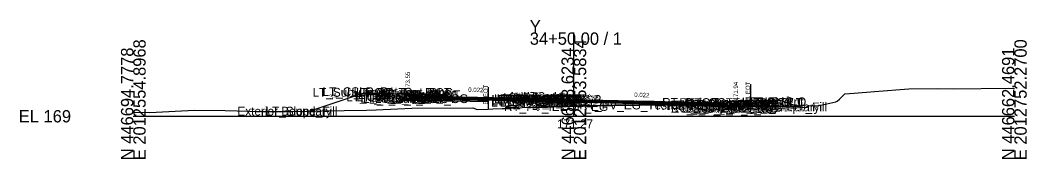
# Model space of a CAD drawing. Extents: x -26 to 3203, y -10 to 9532.
# Drawn here: x 1974.3 to 2202.8, y 8490.3 to 8521.8 of the extents above; entities that cross this region are included whole.
import ezdxf

# ---------------------------------------------------------------- set-up
doc = ezdxf.new("R2010")
doc.units = 0
for name, color, linetype in [('Default', 7, 'Continuous'), ('Exist CMT Pavement', 7, 'Continuous'), ('Exist Cross Section Cell', 7, 'Continuous'), ('Exist XS Center Line Elevation Label', 7, 'Continuous'), ('Exist XS Ground Line', 7, 'Continuous'), ('Prop CMT Conc Surface', 7, 'Continuous'), ('Prop CMT Concrete Structures', 7, 'Continuous'), ('Prop CMT Pvmt Course 1', 7, 'Continuous'), ('Prop CMT Pvmt Course 1 CG', 7, 'Continuous'), ('Prop CMT Pvmt Course 1 Wedge', 7, 'Continuous'), ('Prop CMT Pvmt Course 2', 7, 'Continuous'), ('Prop CMT Pvmt Course 2 Wedge', 7, 'Continuous'), ('Prop CMT Pvmt Course 3', 7, 'Continuous'), ('Prop CMT Pvmt Course 3 Wedge', 7, 'Continuous'), ('Prop CMT Pvmt Surface', 7, 'Continuous'), ('Prop CMT Pvmt Wedge Surface 1', 7, 'Continuous'), ('Prop CMT Pvmt Wedge Surface 2', 7, 'Continuous'), ('Prop CMT Pvmt Wedge Surface 3', 7, 'Continuous'), ('Prop CMT Slope Grass', 7, 'Continuous'), ('Prop CMT Subgrade Earthwork', 7, 'Continuous'), ('Prop XS Hydro Elevations', 7, 'Continuous'), ('Prop XS Label Text', 7, 'Continuous'), ('Prop XS SE Text', 7, 'Continuous'), ('Prop XS Side Slope Text', 7, 'Continuous'), ('Scratch_Level_0', 7, 'Continuous')]:
    doc.layers.add(name, color=color, linetype=linetype)

msp = doc.modelspace()

# ---------------------------------------------------------------- linework, layer by layer
at = {"layer": 'Exist CMT Pavement'}
for points in [[(2114.88, 8502.55), (2096, 8502.18)], [(2132.75, 8502.44), (2114.88, 8502.55)]]:
    msp.add_lwpolyline(points, dxfattribs=at)
at = {"layer": 'Exist Cross Section Cell'}
for p, q in [((2100, 8500), (2100, 8519.04)), ((2000, 8500), (2100, 8500)), ((2100, 8500), (2200, 8500))]:
    msp.add_line(p, q, dxfattribs=at)
at = {"layer": 'Exist XS Ground Line'}
msp.add_lwpolyline([(2000, 8500.9), (2003.73, 8500.84), (2009.52, 8501.12), (2013.86, 8501.36), (2020.88, 8501.27), (2029.09, 8501.06), (2032.82, 8501.04), (2036, 8501.09), (2042.82, 8501.21), (2052.94, 8501.39), (2055.16, 8501.43), (2063.21, 8501.81), (2077.04, 8501.94), (2078.08, 8501.5), (2080.58, 8501.62), (2081.61, 8501.66), (2083.71, 8501.76), (2084.02, 8501.77), (2084.5, 8501.79), (2085.76, 8501.84), (2087.74, 8501.94), (2088.29, 8501.96), (2091.1, 8502.05), (2093.36, 8502.13), (2095.2, 8502.17), (2095.87, 8502.18), (2097.66, 8502.22), (2098.31, 8502.23), (2099.47, 8502.26), (2100, 8502.27), (2100.92, 8502.29), (2102.83, 8502.34), (2103.44, 8502.35), (2106.11, 8502.41), (2106.53, 8502.42), (2108.77, 8502.47), (2109.63, 8502.48), (2111.06, 8502.5), (2112.58, 8502.52), (2113.59, 8502.53), (2114.78, 8502.55), (2116.11, 8502.56), (2117.98, 8502.57), (2118.66, 8502.58), (2118.97, 8502.58), (2119.51, 8502.58), (2121.28, 8502.59), (2121.92, 8502.59), (2123.77, 8502.59), (2125.7, 8502.57), (2126.31, 8502.56), (2127.89, 8502.54), (2128.84, 8502.52), (2129.77, 8502.5), (2130.16, 8502.49), (2130.68, 8502.48), (2131.36, 8502.47), (2133.18, 8502.43), (2133.9, 8502.41), (2136.57, 8502.36), (2137.48, 8502.34), (2138.96, 8502.32), (2140.11, 8502.29), (2141.48, 8502.26), (2143.1, 8502.24), (2144, 8502.22), (2145.26, 8502.2), (2146.53, 8502.19), (2148.3, 8502.16), (2149.06, 8502.15), (2150.83, 8502.11), (2152.56, 8501.98), (2153.31, 8502.43), (2155.37, 8502.34), (2159.47, 8503.31), (2159.81, 8503.4), (2160.31, 8503.88), (2161.52, 8505.09), (2163.61, 8505.24), (2168.23, 8505.63), (2176.01, 8506.24), (2182.45, 8506.34), (2186.15, 8506.22), (2198.64, 8506.35), (2200, 8506.34)], dxfattribs=at)
at = {"layer": 'Prop CMT Conc Surface'}
for points in [[(2057.81, 8505.14), (2052.81, 8505.24)], [(2062.31, 8504.55), (2062.31, 8505.05), (2061.81, 8505.05)], [(2064.31, 8504.59), (2062.31, 8504.55)], [(2134.75, 8503.07), (2136.75, 8502.94)], [(2136.75, 8502.94), (2136.75, 8503.44), (2137.25, 8503.44)], [(2141.25, 8503.53), (2146.25, 8503.63)]]:
    msp.add_lwpolyline(points, dxfattribs=at)
at = {"layer": 'Prop CMT Concrete Structures'}
for points in [[(2052.81, 8504.91), (2052.81, 8505.24)], [(2052.81, 8505.24), (2057.81, 8505.14)], [(2057.81, 8504.81), (2052.81, 8504.91)], [(2057.81, 8505.14), (2057.81, 8504.81)], [(2064.31, 8504.59), (2062.31, 8504.55), (2062.31, 8505.05), (2061.81, 8505.05)], [(2061.81, 8505.05), (2061.81, 8504.06), (2064.31, 8504.01)], [(2064.31, 8504.01), (2064.31, 8504.59)], [(2096, 8503.9), (2095.99, 8504.07), (2095.24, 8504.32), (2094, 8504.43), (2092.76, 8504.41), (2092.01, 8504.16), (2092, 8503.99)], [(2092, 8503.99), (2096, 8503.9)], [(2134.75, 8503.07), (2136.75, 8502.94), (2136.75, 8503.44), (2137.25, 8503.44)], [(2137.25, 8503.44), (2137.25, 8502.43), (2134.75, 8502.48)], [(2134.75, 8502.48), (2134.75, 8503.07)], [(2146.25, 8503.63), (2141.25, 8503.53)], [(2141.25, 8503.53), (2141.25, 8503.2)], [(2141.25, 8503.2), (2146.25, 8503.3)], [(2146.25, 8503.3), (2146.25, 8503.63)]]:
    msp.add_lwpolyline(points, dxfattribs=at)
at = {"layer": 'Prop CMT Pvmt Course 1'}
for points in [[(2092, 8503.99), (2064.31, 8504.59)], [(2064.31, 8504.59), (2064.31, 8504.34)], [(2064.31, 8504.34), (2092, 8503.74)], [(2092, 8503.99), (2096, 8503.9)], [(2092, 8503.74), (2092, 8503.99)], [(2092, 8503.74), (2092, 8503.99)], [(2096, 8503.65), (2092, 8503.74)], [(2096, 8503.9), (2134.75, 8503.07)], [(2096, 8503.65), (2096, 8503.9)], [(2096, 8503.9), (2096, 8503.65)], [(2132.75, 8502.99), (2096, 8503.78)], [(2096, 8503.78), (2096, 8503.65), (2096, 8503.65)], [(2132.75, 8502.86), (2132.75, 8502.99)], [(2134.75, 8502.82), (2133.75, 8502.84)], [(2134.75, 8503.07), (2134.75, 8502.82)]]:
    msp.add_lwpolyline(points, dxfattribs=at)
msp.add_lwpolyline([(2092, 8503.74), (2092, 8503.87), (2092, 8503.87), (2092, 8503.74)], close=True, dxfattribs=at)
at = {"layer": 'Prop CMT Pvmt Course 1 CG'}
for points in [[(2064.31, 8504.01), (2061.31, 8504.07), (2060.99, 8503.75)], [(2060.99, 8503.75), (2064.31, 8503.67)], [(2064.31, 8503.67), (2064.31, 8504.01)], [(2134.75, 8502.48), (2137.75, 8502.42), (2138.09, 8502.08)], [(2134.75, 8502.15), (2134.75, 8502.48)], [(2138.09, 8502.08), (2134.75, 8502.15)]]:
    msp.add_lwpolyline(points, dxfattribs=at)
at = {"layer": 'Prop CMT Pvmt Course 1 Wedge'}
for points in [[(2096, 8503.65), (2096, 8503.78)], [(2096, 8503.78), (2097.66, 8503.74), (2098.31, 8503.73), (2098.37, 8503.73), (2099.47, 8503.7), (2100.92, 8503.67), (2102.83, 8503.63), (2103.44, 8503.62), (2105.89, 8503.57), (2105.99, 8503.56), (2106.11, 8503.56), (2106.53, 8503.55), (2108.6, 8503.51), (2108.77, 8503.5), (2109.63, 8503.49), (2111.06, 8503.45), (2112.58, 8503.42), (2113.59, 8503.4), (2114.78, 8503.37), (2116.11, 8503.35), (2117.98, 8503.3), (2118.66, 8503.29), (2118.97, 8503.28), (2119.51, 8503.27), (2121.04, 8503.24), (2121.18, 8503.24), (2121.28, 8503.23), (2121.92, 8503.22), (2123.52, 8503.18), (2123.77, 8503.18), (2125.7, 8503.14), (2126.31, 8503.12), (2127.89, 8503.09), (2128.84, 8503.07), (2129.77, 8503.05), (2130.16, 8503.04), (2130.68, 8503.03), (2131.36, 8503.02), (2132.75, 8502.99)], [(2133.75, 8502.84), (2133.18, 8502.85), (2131.36, 8502.89), (2130.68, 8502.9), (2130.16, 8502.92), (2129.77, 8502.92), (2128.84, 8502.94), (2127.89, 8502.97), (2126.31, 8503), (2125.7, 8503.01), (2123.77, 8503.05), (2123.52, 8503.06), (2121.92, 8503.09), (2121.28, 8503.11), (2121.18, 8503.11), (2121.04, 8503.11), (2119.51, 8503.15), (2118.97, 8503.16), (2118.66, 8503.16), (2117.98, 8503.18), (2116.11, 8503.22), (2114.78, 8503.25), (2113.59, 8503.27), (2112.58, 8503.3), (2111.06, 8503.33), (2109.63, 8503.36), (2108.77, 8503.38), (2108.6, 8503.38), (2106.53, 8503.43), (2106.11, 8503.44), (2105.99, 8503.44), (2105.89, 8503.44), (2103.44, 8503.49), (2102.83, 8503.51), (2100.92, 8503.55), (2099.47, 8503.58), (2098.37, 8503.6), (2098.31, 8503.6), (2097.66, 8503.62), (2096, 8503.65)], [(2132.75, 8502.99), (2132.75, 8502.86)]]:
    msp.add_lwpolyline(points, dxfattribs=at)
at = {"layer": 'Prop CMT Pvmt Course 2'}
for points in [[(2092, 8503.74), (2064.31, 8504.34)], [(2064.31, 8504.34), (2064.31, 8504.01)], [(2064.31, 8504.01), (2092, 8503.41)], [(2092, 8503.74), (2096, 8503.65)], [(2092, 8503.41), (2092, 8503.74)], [(2092, 8503.41), (2092, 8503.74)], [(2096, 8503.32), (2092, 8503.41)], [(2096, 8503.65), (2096, 8503.32)], [(2132.75, 8502.53), (2132.75, 8502.86)], [(2133.75, 8502.84), (2134.75, 8502.82)], [(2134.75, 8502.48), (2133.75, 8502.51)], [(2134.75, 8502.82), (2134.75, 8502.48)]]:
    msp.add_lwpolyline(points, dxfattribs=at)
at = {"layer": 'Prop CMT Pvmt Course 2 Wedge'}
for points in [[(2096, 8503.65), (2097.66, 8503.62), (2098.31, 8503.6), (2098.37, 8503.6), (2099.47, 8503.58), (2100.92, 8503.55), (2102.83, 8503.51), (2103.44, 8503.49), (2105.89, 8503.44), (2105.99, 8503.44), (2106.11, 8503.44), (2106.53, 8503.43), (2108.6, 8503.38), (2108.77, 8503.38), (2109.63, 8503.36), (2111.06, 8503.33), (2112.58, 8503.3), (2113.59, 8503.27), (2114.78, 8503.25), (2116.11, 8503.22), (2117.98, 8503.18), (2118.66, 8503.16), (2118.97, 8503.16), (2119.51, 8503.15), (2121.04, 8503.11), (2121.18, 8503.11), (2121.28, 8503.11), (2121.92, 8503.09), (2123.52, 8503.06), (2123.77, 8503.05), (2125.7, 8503.01), (2126.31, 8503), (2127.89, 8502.97), (2128.84, 8502.94), (2129.77, 8502.92), (2130.16, 8502.92), (2130.68, 8502.9), (2131.36, 8502.89), (2133.18, 8502.85), (2133.75, 8502.84)], [(2096, 8503.32), (2096, 8503.65)], [(2133.75, 8502.51), (2133.18, 8502.52), (2131.36, 8502.56), (2130.68, 8502.57), (2130.16, 8502.58), (2129.77, 8502.59), (2128.84, 8502.61), (2127.89, 8502.63), (2126.31, 8502.67), (2125.7, 8502.68), (2123.77, 8502.72), (2123.52, 8502.73), (2121.92, 8502.76), (2121.28, 8502.77), (2121.18, 8502.78), (2121.04, 8502.78), (2119.51, 8502.81), (2118.97, 8502.82), (2118.66, 8502.83), (2117.98, 8502.85), (2116.11, 8502.89), (2114.78, 8502.92), (2113.59, 8502.94), (2112.58, 8502.96), (2111.06, 8503), (2109.63, 8503.03), (2108.77, 8503.05), (2108.6, 8503.05), (2106.53, 8503.09), (2106.11, 8503.1), (2105.99, 8503.11), (2105.89, 8503.11), (2103.44, 8503.16), (2102.83, 8503.17), (2100.92, 8503.22), (2099.47, 8503.25), (2098.37, 8503.27), (2098.31, 8503.27), (2097.66, 8503.29), (2096, 8503.32)], [(2132.75, 8502.86), (2132.75, 8502.53)]]:
    msp.add_lwpolyline(points, dxfattribs=at)
at = {"layer": 'Prop CMT Pvmt Course 3'}
for points in [[(2092, 8503.41), (2064.31, 8504.01)], [(2064.31, 8504.01), (2064.31, 8503.67)], [(2064.31, 8503.67), (2080.58, 8503.32)], [(2092, 8503.41), (2096, 8503.32)], [(2132.75, 8502.19), (2132.75, 8502.53)], [(2134.75, 8502.15), (2132.75, 8502.19)], [(2133.75, 8502.51), (2134.75, 8502.48)], [(2134.75, 8502.48), (2134.75, 8502.15)]]:
    msp.add_lwpolyline(points, dxfattribs=at)
at = {"layer": 'Prop CMT Pvmt Course 3 Wedge'}
for points in [[(2096, 8503.32), (2097.66, 8503.29), (2098.31, 8503.27), (2098.37, 8503.27), (2099.47, 8503.25), (2100.92, 8503.22), (2102.83, 8503.17), (2103.44, 8503.16), (2105.89, 8503.11), (2105.99, 8503.11), (2106.11, 8503.1), (2106.53, 8503.09), (2108.6, 8503.05), (2108.77, 8503.05), (2109.63, 8503.03), (2111.06, 8503), (2112.58, 8502.96), (2113.59, 8502.94), (2114.78, 8502.92), (2116.11, 8502.89), (2117.98, 8502.85), (2118.66, 8502.83), (2118.97, 8502.82), (2119.51, 8502.81), (2121.04, 8502.78), (2121.18, 8502.78), (2121.28, 8502.77), (2121.92, 8502.76), (2123.52, 8502.73), (2123.77, 8502.72), (2125.7, 8502.68), (2126.31, 8502.67), (2127.89, 8502.63), (2128.84, 8502.61), (2129.77, 8502.59), (2130.16, 8502.58), (2130.68, 8502.57), (2131.36, 8502.56), (2133.18, 8502.52), (2133.75, 8502.51)], [(2133.75, 8502.42), (2133.18, 8502.43), (2131.36, 8502.47), (2130.68, 8502.48), (2130.16, 8502.49), (2129.77, 8502.5), (2128.84, 8502.52), (2127.89, 8502.54), (2126.31, 8502.56), (2125.7, 8502.57), (2123.77, 8502.59), (2123.52, 8502.59), (2121.92, 8502.59), (2121.28, 8502.59), (2121.18, 8502.59), (2121.04, 8502.59), (2119.51, 8502.58), (2118.97, 8502.58), (2118.66, 8502.58), (2117.98, 8502.57), (2116.11, 8502.56), (2114.78, 8502.55), (2113.59, 8502.53), (2112.58, 8502.52), (2111.06, 8502.5), (2109.63, 8502.48), (2108.77, 8502.47), (2108.6, 8502.47), (2106.53, 8502.42), (2106.11, 8502.41), (2105.99, 8502.41), (2105.89, 8502.41), (2103.44, 8502.35), (2102.83, 8502.34), (2100.92, 8502.29), (2099.47, 8502.26), (2098.37, 8502.24), (2098.31, 8502.23), (2097.66, 8502.22), (2096, 8502.18)], [(2132.75, 8502.53), (2132.75, 8502.44)]]:
    msp.add_lwpolyline(points, dxfattribs=at)
at = {"layer": 'Prop CMT Pvmt Surface'}
for points in [[(2092, 8503.99), (2064.31, 8504.59)], [(2092, 8503.99), (2096, 8503.9)], [(2096, 8503.9), (2134.75, 8503.07)]]:
    msp.add_lwpolyline(points, dxfattribs=at)
at = {"layer": 'Prop CMT Pvmt Wedge Surface 1'}
for points in [[(2096, 8503.9), (2096, 8503.65), (2096, 8503.65), (2096, 8503.78)], [(2096, 8503.78), (2132.75, 8502.99)], [(2132.75, 8502.99), (2132.75, 8502.86)], [(2133.75, 8502.84), (2134.75, 8502.82)], [(2134.75, 8502.82), (2134.75, 8503.07)]]:
    msp.add_lwpolyline(points, dxfattribs=at)
at = {"layer": 'Prop CMT Pvmt Wedge Surface 2'}
for points in [[(2096, 8503.9), (2096, 8503.65)], [(2096, 8503.65), (2134.75, 8502.82)], [(2134.75, 8502.82), (2134.75, 8503.07)]]:
    msp.add_lwpolyline(points, dxfattribs=at)
at = {"layer": 'Prop CMT Pvmt Wedge Surface 3'}
for points in [[(2096, 8503.9), (2096, 8503.32)], [(2096, 8503.32), (2134.75, 8502.48)], [(2134.75, 8502.48), (2134.75, 8503.07)]]:
    msp.add_lwpolyline(points, dxfattribs=at)
at = {"layer": 'Prop CMT Slope Grass'}
for points in [[(2061.81, 8505.05), (2052.31, 8505.24), (2040.07, 8501.16)], [(2137.25, 8503.44), (2146.25, 8503.62)], [(2146.25, 8503.62), (2146.75, 8503.63), (2151.46, 8502.06)]]:
    msp.add_lwpolyline(points, dxfattribs=at)
at = {"layer": 'Prop CMT Subgrade Earthwork'}
for p, q in [((2080.58, 8503.32), (2080.58, 8501.62)), ((2132.75, 8502.44), (2132.75, 8502.19))]:
    msp.add_line(p, q, dxfattribs=at)
for points in [[(2064.31, 8503.67), (2060.99, 8503.75), (2059.64, 8505.1)], [(2080.58, 8503.32), (2064.31, 8503.67)], [(2132.75, 8502.19), (2134.75, 8502.15)], [(2134.75, 8502.15), (2138.09, 8502.08), (2139.5, 8503.49)]]:
    msp.add_lwpolyline(points, dxfattribs=at)
at = {"layer": 'Prop XS Label Text'}
for p, q in [((2080.58, 8506.62), (2080.58, 8501.62)), ((2140.11, 8507.29), (2140.11, 8502.29))]:
    msp.add_line(p, q, dxfattribs=at)

# ---------------------------------------------------------------- texts
at = {"layer": 'Default'}
msp.add_text('-', height=0.0001, dxfattribs=at).set_placement((2000, 8500))
at = {"layer": 'Exist Cross Section Cell'}
for s, p in [('Y', (2090, 8519.04)), ('34+50.00 / 1', (2090, 8516.24)), ('EL 169', (1974, 8498.6))]:
    msp.add_text(s, height=2.8, dxfattribs=at).set_placement(p)
for s, p in [('N 446694.7778', (2000, 8490)), ('E 2012554.8968', (2002.8, 8490)), ('N 446678.6234', (2100, 8490)), ('E 2012653.5834', (2102.8, 8490)), ('N 446662.4691', (2200, 8490)), ('E 2012752.2700', (2202.8, 8490))]:
    msp.add_text(s, height=2.8, rotation=90, dxfattribs=at).set_placement(p)
at = {"layer": 'Exist XS Center Line Elevation Label'}
msp.add_text('171.27', height=2, dxfattribs=at).set_placement((2096.18, 8497.27))
at = {"layer": 'Prop XS Hydro Elevations'}
for s, p in [('173.55', (2062.81, 8505.9)), ('171.94', (2137.25, 8503.6))]:
    msp.add_text(s, height=1, rotation=90, dxfattribs=at).set_placement(p)
at = {"layer": 'Prop XS Label Text'}
for p in [(2080.48, 8502.64), (2140.01, 8503.32)]:
    msp.add_text('E. EOT', height=1, rotation=90, dxfattribs=at).set_placement(p)
at = {"layer": 'Prop XS SE Text'}
for p in [(2076.01, 8505.55), (2113.7, 8504.39)]:
    msp.add_text('0.022', height=1, rotation=358.223, dxfattribs=at).set_placement(p)
at = {"layer": 'Prop XS Side Slope Text'}
for rotation, p in [(18.4349, (2044.68, 8503.84)), (341.5651, (2147.98, 8503.67))]:
    msp.add_text('3:1', height=1, rotation=rotation, dxfattribs=at).set_placement(p)
at = {"layer": 'Scratch_Level_0'}
for s, p in [('LT_Sub_Trench_Out_DLT', (2040.69, 8504.44)), ('LT_CSLP_Pnt', (2042.95, 8504.58)), ('LT_CG_Top_Face', (2050.04, 8504.39)), ('LT_CG_Top_BOC', (2050.56, 8504.39)), ('LT_CG1_Shelf_Out', (2048.33, 8503.42)), ('LT_CG_Bot_BOC', (2050.6, 8503.41)), ('LT_CG_Top_Gut', (2051.02, 8503.89)), ('LT_Sub_OEOP', (2051.57, 8503.1)), ('LT_Sub_OEOT_CG', (2052.15, 8502.99)), ('LT_CG_Bot_IE', (2054.69, 8503.33)), ('LT_Sub_OEOT', (2054.86, 8502.99)), ('LT_PV2_OEOT', (2054.95, 8503.66)), ('LT_PV3_OEOT', (2054.95, 8503.33)), ('LT_PV1_OEOT', (2055.52, 8503.91)), ('LT_Sub_OEEOP', (2081.21, 8502.15)), ('LT_PV2_OEEOP', (2081.31, 8502.82)), ('LT_PV3_OEEOP', (2081.31, 8502.48)), ('LT_PV1_OEEOP', (2081.87, 8502.94)), ('LT_PV2_IEEOP', (2081.95, 8502.82)), ('LT_PV1_IEEOP', (2082.52, 8502.94)), ('LT_PV2_PGL1', (2082.88, 8502.82)), ('LT_PV3_PGL1', (2082.88, 8502.48)), ('LT_PV2_PGL', (2083.21, 8502.82)), ('LT_PV4_PGL', (2083.21, 8502.15)), ('LT_PV1_PGL', (2083.78, 8503.07)), ('MI_Face In', (2083.9, 8503.23)), ('MI_Top In', (2085.61, 8503.48)), ('RT_PV2_IEEOP', (2085.91, 8502.69)), ('RT_PV3_IEEOP', (2085.91, 8502.36)), ('MI_Face Out', (2086.26, 8503.11)), ('MI_Top Out', (2086.47, 8503.36)), ('RT_PV1_IEEOP', (2086.47, 8502.82)), ('RT_PV2_PGL1', (2086.83, 8502.69)), ('RT_PV3_PGL1', (2086.83, 8502.36)), ('MI_Crown', (2087.07, 8503.51)), ('RT_PV2_PGL', (2087.17, 8502.69)), ('RT_PV3_PGL', (2087.17, 8502.36)), ('RT_PV4_PGL', (2087.17, 8502.03)), ('MI_Bot Out', (2087.26, 8502.94)), ('RT_PV1_PGL', (2087.73, 8502.94)), ('RT_Sub_Trench_Out_DLT', (2120.04, 8502.14)), ('RT_CG_Top_Face', (2123.96, 8502.1)), ('RT_PV1_OEOT', (2125.44, 8501.74)), ('RT_CG_Top_BOC', (2125.49, 8502.1)), ('RT_Shld_O', (2138.79, 8502.28)), ('CSLP_Pnt', (2139.62, 8502.29)), ('Exterior Boundary', (2023.63, 8500.15)), ('LT_Slope_Fill', (2030, 8500.15)), ('RT_PV_IEEOP_EG', (2084.14, 8501.18)), ('RT_PV_EG_TestPt', (2101.24, 8501.55)), ('RT_PV_Sub_Tie_Out', (2118.63, 8501.42)), ('RT_PV_OEEOP_EG', (2121.25, 8501.42)), ('RT_Sub_OEOT_CG', (2122.07, 8500.82)), ('RT_Sub_OEEOP', (2122.92, 8500.85)), ('RT_PV2_OEEOP', (2123.01, 8501.52)), ('RT_PV3_OEEOP', (2123.01, 8501.19)), ('RT_PV1_OEEOP', (2123.58, 8501.65)), ('RT_CG1_Shelf_Out', (2124.25, 8501.06)), ('RT_CG_Bot_IE', (2124.62, 8501.16)), ('RT_Sub_OEOT', (2124.78, 8500.82)), ('RT_PV2_OEOT', (2124.88, 8501.49)), ('RT_PV3_OEOT', (2124.88, 8501.16)), ('RT_CG_Top_Gut', (2124.94, 8501.6)), ('RT_CG_Bot_BOC', (2125.52, 8501.08)), ('RT_Sub_OEOP', (2128.16, 8500.72)), ('Exterior Boundary', (2134.39, 8501.12)), ('RT_Slope_Fill', (2140.72, 8501.12))]:
    msp.add_text(s, height=2, dxfattribs=at).set_placement(p)

doc.saveas('drawing.dxf')
